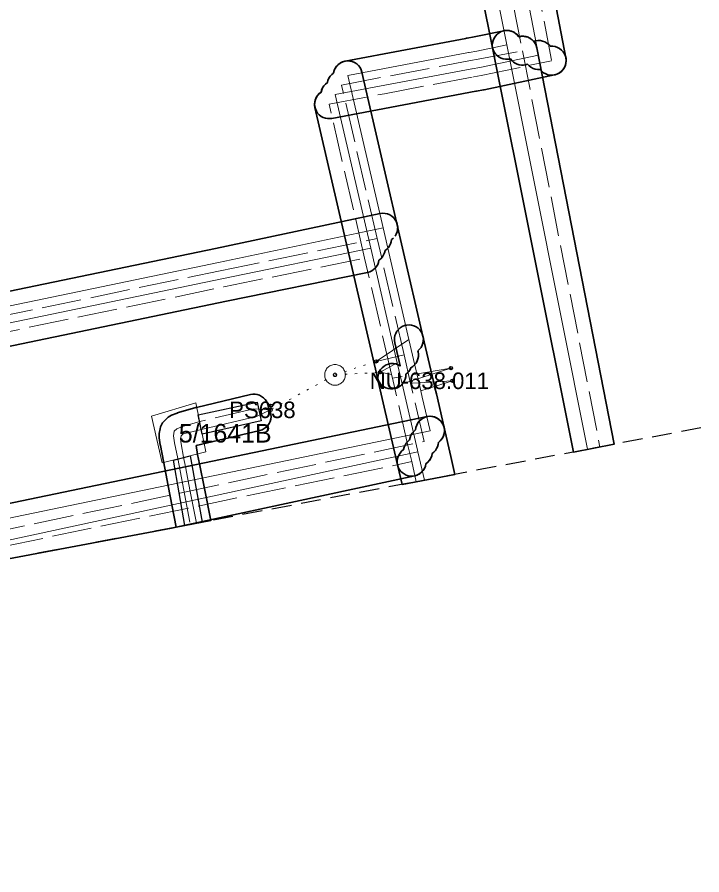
# Model space of a CAD drawing. Extents: x -452602 to -451136, y -1100088 to -1099653.
# Drawn here: x -451882.27 to -451849.14, y -1099973.17 to -1099931.68 of the extents above; entities that cross this region are included whole.
import ezdxf

# ---------------------------------------------------------------- set-up
doc = ezdxf.new("R2010")
doc.units = 0
doc.header["$LTSCALE"] = 0.32
doc.header["$PDMODE"] = 32
doc.header["$PDSIZE"] = 0.16
for name, pattern in [('DOTTED', [1.5, 0.3, -1.2]), ('LONG_DASHED', [7.5, 6, -1.5]), ('MEDIUM_DASHED', [4.5, 3, -1.5])]:
    doc.linetypes.add(name, pattern=pattern)
for name, color, linetype in [('1', 7, 'Continuous'), ('4', 7, 'Continuous'), ('7', 7, 'Continuous')]:
    doc.layers.add(name, color=color, linetype=linetype)
for name, color, linetype, lineweight in [('2', 7, 'Continuous', 13), ('3', 7, 'Continuous', 25), ('5', 7, 'Continuous', 13), ('62', 7, 'MEDIUM_DASHED', 25), ('8', 7, 'Continuous', 35)]:
    doc.layers.add(name, color=color, linetype=linetype, lineweight=lineweight)

msp = doc.modelspace()

# ---------------------------------------------------------------- linework, layer by layer
at = {"layer": '1'}
for p in [(-451864.903, -1099948.331), (-451864.706, -1099948.857)]:
    msp.add_point(p, dxfattribs=at)
at = {"layer": '2'}
for p, q in [((-451864.778, -1099902.248), (-451858.58, -1099933.019)), ((-451862.992, -1099903.201), (-451857.038, -1099933.512)), ((-451858.58, -1099933.019), (-451854.67, -1099952.584)), ((-451863.315, -1099947.27), (-451864.563, -1099941.87)), ((-451863.876, -1099948.397), (-451865.156, -1099942.858)), ((-451863.315, -1099947.27), (-451864.903, -1099948.331)), ((-451862.738, -1099949.763), (-451863.315, -1099947.27)), ((-451863.876, -1099948.397), (-451864.706, -1099948.857)), ((-451863.641, -1099949.411), (-451863.876, -1099948.397)), ((-451861.281, -1099948.654), (-451863.641, -1099949.411)), ((-451862.738, -1099949.763), (-451861.21, -1099949.269)), ((-451870.689, -1099950.989), (-451870.007, -1099950.674)), ((-451862.562, -1099954.077), (-451862.88, -1099952.702))]:
    msp.add_line(p, q, dxfattribs=at)
at = {"layer": '2', "linetype": 'LONG_DASHED'}
for p, q in [((-451863.866, -1099902.804), (-451857.821, -1099933.303)), ((-451862.199, -1099903.597), (-451856.41, -1099933.788)), ((-451857.821, -1099933.303), (-451854.074, -1099952.472)), ((-451863.551, -1099948.021), (-451864.854, -1099942.386)), ((-451864.156, -1099948.964), (-451865.455, -1099943.341)), ((-451863.551, -1099948.021), (-451864.903, -1099948.331)), ((-451863.233, -1099949.395), (-451863.551, -1099948.021)), ((-451864.156, -1099948.964), (-451864.706, -1099948.857)), ((-451864.115, -1099949.137), (-451864.156, -1099948.964)), ((-451861.281, -1099948.654), (-451864.115, -1099949.137)), ((-451861.21, -1099949.269), (-451863.233, -1099949.395)), ((-451862.583, -1099952.206), (-451863.233, -1099949.395)), ((-451870.82, -1099950.62), (-451870.007, -1099950.674)), ((-451862.956, -1099954.151), (-451863.18, -1099953.181))]:
    msp.add_line(p, q, dxfattribs=at)
at = {"layer": '2', "linetype": 'DOTTED'}
for q in [(-451864.903, -1099948.331), (-451870.007, -1099950.674), (-451864.706, -1099948.857)]:
    msp.add_line((-451866.89, -1099948.984), q, dxfattribs=at)
at = {"layer": '2'}
for points in [[(-451860.424, -1099933.39), (-451860.405, -1099933.386), (-451860.035, -1099933.326), (-451858.58, -1099933.019)], [(-451864.563, -1099941.87), (-451866.267, -1099934.499), (-451860.424, -1099933.39)], [(-451860.252, -1099934.173), (-451859.888, -1099934.114), (-451857.038, -1099933.512)], [(-451865.156, -1099942.858), (-451866.875, -1099935.429), (-451860.266, -1099934.175), (-451860.252, -1099934.173)], [(-451864.563, -1099941.87), (-451872.522, -1099943.554), (-451901.925, -1099949.652), (-451902.376, -1099947.344)], [(-451865.156, -1099942.858), (-451872.357, -1099944.337), (-451872.363, -1099944.337), (-451902.483, -1099950.597), (-451903.107, -1099947.495)], [(-451862.88, -1099952.702), (-451862.897, -1099952.63), (-451863.641, -1099949.411)], [(-451862.294, -1099951.684), (-451862.669, -1099950.062), (-451862.738, -1099949.763)], [(-451873.593, -1099956.163), (-451873.896, -1099954.62), (-451874.13, -1099953.427), (-451874.222, -1099952.958), (-451874.33, -1099952.315), (-451874.369, -1099952.078), (-451874.333, -1099951.934), (-451874.231, -1099951.841), (-451874.028, -1099951.784), (-451873.292, -1099951.606), (-451870.689, -1099950.989)], [(-451886.379, -1099958.581), (-451886.715, -1099956.758), (-451862.294, -1099951.684)], [(-451885.428, -1099958.401), (-451885.603, -1099957.604), (-451862.88, -1099952.702)]]:
    msp.add_lwpolyline(points, dxfattribs=at)
at = {"layer": '2', "linetype": 'LONG_DASHED'}
for points in [[(-451860.339, -1099933.78), (-451860.336, -1099933.78), (-451859.962, -1099933.719), (-451857.821, -1099933.303)], [(-451864.854, -1099942.386), (-451866.571, -1099934.964), (-451860.339, -1099933.78)], [(-451860.167, -1099934.563), (-451859.815, -1099934.506), (-451856.41, -1099933.788)], [(-451864.495, -1099935.384), (-451860.196, -1099934.568), (-451860.167, -1099934.563)], [(-451865.455, -1099943.341), (-451867.178, -1099935.892), (-451864.495, -1099935.384)], [(-451902.749, -1099947.447), (-451902.206, -1099950.14), (-451872.441, -1099943.945), (-451872.44, -1099943.945), (-451864.854, -1099942.386)], [(-451903.519, -1099947.567), (-451902.827, -1099951.079), (-451872.285, -1099944.73), (-451872.275, -1099944.728), (-451865.455, -1099943.341)], [(-451863.18, -1099953.181), (-451863.376, -1099952.332), (-451864.115, -1099949.137)], [(-451870.82, -1099950.62), (-451873.429, -1099951.239), (-451874.268, -1099951.479), (-451874.535, -1099951.585), (-451874.663, -1099951.713), (-451874.699, -1099951.934), (-451874.65, -1099952.264), (-451874.501, -1099953.029), (-451874.273, -1099954.214), (-451873.891, -1099956.219)], [(-451885.867, -1099958.484), (-451886.133, -1099957.181), (-451862.583, -1099952.206)], [(-451885.135, -1099958.345), (-451885.261, -1099957.769), (-451863.18, -1099953.181)]]:
    msp.add_lwpolyline(points, dxfattribs=at)
at = {"layer": '3', "lineweight": 13}
msp.add_lwpolyline([(-451875.25, -1099953.239), (-451875.774, -1099950.975), (-451873.63, -1099950.339), (-451873.14, -1099952.699)], close=True, dxfattribs=at)
at = {"layer": '3'}
for points in [[(-451873.51, -1099950.913), (-451870.663, -1099950.3), (-451870.462, -1099951.208), (-451873.317, -1099951.843)], [(-451874.154, -1099956.269), (-451874.711, -1099953.102), (-451873.897, -1099952.893), (-451873.317, -1099956.11)]]:
    msp.add_lwpolyline(points, close=True, dxfattribs=at)
at = {"layer": '4'}
for p in [(-451861.281, -1099948.654), (-451861.21, -1099949.269), (-451870.007, -1099950.674)]:
    msp.add_point(p, dxfattribs=at)
at = {"layer": '5'}
for points in [[(-451866.39, -1099948.984), (-451866.393, -1099948.932), (-451866.401, -1099948.88), (-451866.415, -1099948.829), (-451866.433, -1099948.781), (-451866.457, -1099948.734), (-451866.486, -1099948.69), (-451866.519, -1099948.65), (-451866.556, -1099948.613), (-451866.596, -1099948.579), (-451866.64, -1099948.551), (-451866.687, -1099948.527), (-451866.736, -1099948.508), (-451866.786, -1099948.494), (-451866.838, -1099948.487), (-451866.89, -1099948.484), (-451866.942, -1099948.487), (-451866.994, -1099948.494), (-451867.045, -1099948.508), (-451867.093, -1099948.527), (-451867.14, -1099948.551), (-451867.184, -1099948.579), (-451867.225, -1099948.613), (-451867.262, -1099948.65), (-451867.295, -1099948.69), (-451867.323, -1099948.734), (-451867.347, -1099948.781), (-451867.366, -1099948.829), (-451867.379, -1099948.88), (-451867.387, -1099948.932), (-451867.39, -1099948.984), (-451867.387, -1099949.035), (-451867.379, -1099949.088), (-451867.366, -1099949.139), (-451867.347, -1099949.187), (-451867.323, -1099949.234), (-451867.295, -1099949.278), (-451867.262, -1099949.319), (-451867.225, -1099949.356), (-451867.184, -1099949.389), (-451867.14, -1099949.417), (-451867.093, -1099949.44), (-451867.045, -1099949.46), (-451866.994, -1099949.473), (-451866.942, -1099949.481), (-451866.89, -1099949.484), (-451866.838, -1099949.481), (-451866.786, -1099949.473), (-451866.736, -1099949.46), (-451866.687, -1099949.44), (-451866.64, -1099949.417), (-451866.596, -1099949.389), (-451866.556, -1099949.356), (-451866.519, -1099949.319), (-451866.486, -1099949.278), (-451866.457, -1099949.234), (-451866.433, -1099949.187), (-451866.415, -1099949.139), (-451866.401, -1099949.088), (-451866.393, -1099949.035)], [(-451866.808, -1099948.984), (-451866.808, -1099948.974), (-451866.81, -1099948.967), (-451866.812, -1099948.959), (-451866.815, -1099948.951), (-451866.819, -1099948.943), (-451866.824, -1099948.936), (-451866.829, -1099948.929), (-451866.835, -1099948.923), (-451866.842, -1099948.917), (-451866.849, -1099948.913), (-451866.857, -1099948.909), (-451866.865, -1099948.906), (-451866.873, -1099948.903), (-451866.881, -1099948.902), (-451866.89, -1099948.902), (-451866.899, -1099948.902), (-451866.907, -1099948.903), (-451866.915, -1099948.906), (-451866.923, -1099948.909), (-451866.931, -1099948.913), (-451866.938, -1099948.917), (-451866.945, -1099948.923), (-451866.951, -1099948.929), (-451866.957, -1099948.936), (-451866.961, -1099948.943), (-451866.965, -1099948.951), (-451866.968, -1099948.959), (-451866.97, -1099948.967), (-451866.972, -1099948.974), (-451866.972, -1099948.984), (-451866.972, -1099948.993), (-451866.97, -1099949.001), (-451866.968, -1099949.008), (-451866.965, -1099949.017), (-451866.961, -1099949.025), (-451866.957, -1099949.032), (-451866.951, -1099949.038), (-451866.945, -1099949.045), (-451866.938, -1099949.051), (-451866.931, -1099949.055), (-451866.923, -1099949.059), (-451866.915, -1099949.062), (-451866.907, -1099949.064), (-451866.899, -1099949.065), (-451866.89, -1099949.065), (-451866.881, -1099949.065), (-451866.873, -1099949.064), (-451866.865, -1099949.062), (-451866.857, -1099949.059), (-451866.849, -1099949.055), (-451866.842, -1099949.051), (-451866.835, -1099949.045), (-451866.829, -1099949.038), (-451866.824, -1099949.032), (-451866.819, -1099949.025), (-451866.815, -1099949.017), (-451866.812, -1099949.008), (-451866.81, -1099949.001), (-451866.808, -1099948.993)]]:
    msp.add_lwpolyline(points, close=True, dxfattribs=at)
at = {"layer": '62'}
msp.add_lwpolyline([(-451137.485, -1099816.961), (-452572.169, -1100088.267), (-452602.314, -1099919.678), (-451137.485, -1099652.838), (-451136.368, -1099701.963)], close=True, dxfattribs=at)
at = {"layer": '7'}
msp.add_point((-451869.987, -1099950.476), dxfattribs=at)
at = {"layer": '8'}
for points in [[(-451861.511, -1099903.466), (-451855.722, -1099933.656), (-451855.71, -1099933.773), (-451855.717, -1099933.89), (-451855.744, -1099934.005), (-451855.789, -1099934.113), (-451855.853, -1099934.212), (-451855.931, -1099934.299), (-451856.024, -1099934.372), (-451856.127, -1099934.428), (-451856.238, -1099934.467), (-451856.354, -1099934.486), (-451856.471, -1099934.486), (-451856.586, -1099934.465), (-451856.697, -1099934.427), (-451856.799, -1099934.37), (-451856.891, -1099934.296), (-451856.969, -1099934.209), (-451856.983, -1099934.21), (-451857.094, -1099934.21), (-451857.205, -1099934.192), (-451857.311, -1099934.157), (-451857.41, -1099934.106), (-451857.5, -1099934.039), (-451857.577, -1099933.959), (-451857.67, -1099933.986), (-451857.765, -1099934.001), (-451857.87, -1099934.001), (-451857.974, -1099933.986), (-451858.075, -1099933.955), (-451858.17, -1099933.909), (-451858.257, -1099933.85), (-451858.334, -1099933.778), (-451858.4, -1099933.696), (-451858.462, -1099933.709), (-451858.524, -1099933.717), (-451858.637, -1099933.717), (-451858.748, -1099933.699), (-451858.855, -1099933.663), (-451858.955, -1099933.611), (-451859.045, -1099933.543), (-451859.123, -1099933.461), (-451859.187, -1099933.368), (-451859.235, -1099933.266), (-451859.266, -1099933.158), (-451865.465, -1099902.386)], [(-451858.025, -1099932.593), (-451858.002, -1099932.625), (-451857.954, -1099932.616), (-451857.912, -1099932.609), (-451857.866, -1099932.604), (-451857.821, -1099932.603), (-451857.775, -1099932.604), (-451857.729, -1099932.609), (-451857.684, -1099932.616), (-451857.64, -1099932.627), (-451857.596, -1099932.64), (-451857.553, -1099932.656), (-451857.511, -1099932.675), (-451857.471, -1099932.697), (-451857.432, -1099932.721), (-451857.395, -1099932.747), (-451857.359, -1099932.776), (-451857.326, -1099932.808), (-451857.294, -1099932.841), (-451857.288, -1099932.85), (-451857.183, -1099932.827), (-451857.07, -1099932.812), (-451856.956, -1099932.815), (-451856.844, -1099932.837), (-451856.737, -1099932.877), (-451856.638, -1099932.933), (-451856.549, -1099933.005), (-451856.473, -1099933.09), (-451856.355, -1099933.089), (-451856.239, -1099933.107), (-451856.127, -1099933.144), (-451856.023, -1099933.2), (-451855.929, -1099933.273), (-451855.85, -1099933.36), (-451855.786, -1099933.459), (-451855.739, -1099933.568), (-451855.712, -1099933.683), (-451855.704, -1099933.8), (-451855.717, -1099933.918), (-451855.748, -1099934.032), (-451855.799, -1099934.138), (-451855.867, -1099934.235), (-451855.95, -1099934.319), (-451856.046, -1099934.388), (-451856.152, -1099934.44), (-451856.265, -1099934.473), (-451859.671, -1099935.191), (-451859.686, -1099935.194), (-451859.704, -1099935.197), (-451860.049, -1099935.253), (-451860.056, -1099935.254), (-451860.072, -1099935.257), (-451867.047, -1099936.58), (-451867.122, -1099936.59), (-451867.237, -1099936.59), (-451867.35, -1099936.571), (-451867.459, -1099936.533), (-451867.56, -1099936.478), (-451867.651, -1099936.408), (-451867.729, -1099936.323), (-451867.792, -1099936.227), (-451867.839, -1099936.121), (-451867.868, -1099936.01), (-451867.877, -1099935.895), (-451867.868, -1099935.78), (-451867.84, -1099935.668), (-451867.795, -1099935.563), (-451867.732, -1099935.466), (-451867.655, -1099935.381), (-451867.564, -1099935.309), (-451867.536, -1099935.199), (-451867.49, -1099935.094), (-451867.427, -1099934.999), (-451867.35, -1099934.915), (-451867.26, -1099934.844), (-451867.232, -1099934.734), (-451867.186, -1099934.63), (-451867.124, -1099934.535), (-451867.047, -1099934.451), (-451866.957, -1099934.38), (-451866.927, -1099934.263), (-451866.876, -1099934.153), (-451866.807, -1099934.053), (-451866.722, -1099933.967), (-451866.624, -1099933.896), (-451866.515, -1099933.844), (-451866.398, -1099933.811), (-451860.568, -1099932.706), (-451860.554, -1099932.703), (-451860.541, -1099932.7), (-451860.489, -1099932.692), (-451860.164, -1099932.638), (-451858.725, -1099932.335), (-451858.717, -1099932.333), (-451858.671, -1099932.325), (-451858.626, -1099932.321), (-451858.58, -1099932.319), (-451858.534, -1099932.321), (-451858.489, -1099932.325), (-451858.443, -1099932.333)], [(-451858.399, -1099932.343), (-451858.355, -1099932.357), (-451858.312, -1099932.373), (-451858.27, -1099932.392), (-451858.23, -1099932.413), (-451858.191, -1099932.437), (-451858.154, -1099932.464), (-451858.119, -1099932.493), (-451858.085, -1099932.524), (-451858.054, -1099932.558), (-451858.025, -1099932.593)], [(-451901.374, -1099948.823), (-451872.665, -1099942.868), (-451864.708, -1099941.185), (-451864.589, -1099941.169), (-451864.469, -1099941.174), (-451864.351, -1099941.199), (-451864.24, -1099941.244), (-451864.137, -1099941.307), (-451864.048, -1099941.387), (-451863.973, -1099941.481), (-451863.915, -1099941.587), (-451863.876, -1099941.701), (-451863.858, -1099941.82), (-451863.86, -1099941.94), (-451863.882, -1099942.058), (-451863.925, -1099942.171), (-451863.986, -1099942.274)], [(-451864.064, -1099942.366), (-451864.156, -1099942.443), (-451864.173, -1099942.546), (-451864.204, -1099942.647), (-451864.251, -1099942.741), (-451864.31, -1099942.827), (-451864.382, -1099942.903), (-451864.465, -1099942.968), (-451864.492, -1099943.079), (-451864.537, -1099943.183), (-451864.597, -1099943.28), (-451864.673, -1099943.365), (-451864.762, -1099943.436), (-451864.784, -1099943.542), (-451864.823, -1099943.642), (-451864.877, -1099943.736), (-451864.945, -1099943.82), (-451865.024, -1099943.893), (-451865.114, -1099943.953), (-451865.212, -1099943.998), (-451865.316, -1099944.027), (-451872.136, -1099945.415), (-451872.145, -1099945.416)], [(-451872.145, -1099945.416), (-451902.685, -1099951.764)], [(-451886.857, -1099956.072), (-451862.436, -1099950.998), (-451862.318, -1099950.984), (-451862.2, -1099950.99), (-451862.083, -1099951.016), (-451861.973, -1099951.061), (-451861.873, -1099951.125), (-451861.784, -1099951.204), (-451861.71, -1099951.297), (-451861.653, -1099951.402), (-451861.615, -1099951.514), (-451861.596, -1099951.632), (-451861.597, -1099951.751), (-451861.619, -1099951.868), (-451861.659, -1099951.979), (-451861.719, -1099952.083), (-451861.795, -1099952.174), (-451861.885, -1099952.252), (-451861.899, -1099952.355), (-451861.929, -1099952.456), (-451861.974, -1099952.551), (-451862.032, -1099952.638), (-451862.103, -1099952.715), (-451862.184, -1099952.782), (-451862.208, -1099952.901), (-451862.253, -1099953.014), (-451862.316, -1099953.118), (-451862.397, -1099953.209), (-451862.492, -1099953.285), (-451862.52, -1099953.402), (-451862.568, -1099953.513), (-451862.633, -1099953.614), (-451862.715, -1099953.701), (-451862.811, -1099953.774), (-451862.918, -1099953.829), (-451863.033, -1099953.865), (-451874.807, -1099956.392), (-451887.066, -1099958.711)]]:
    msp.add_lwpolyline(points, dxfattribs=at)
for points in [[(-451858.003, -1099932.627), (-451857.89, -1099932.606), (-451857.776, -1099932.604), (-451857.662, -1099932.621), (-451857.553, -1099932.656), (-451857.451, -1099932.709), (-451857.358, -1099932.777), (-451857.279, -1099932.86), (-451857.214, -1099932.954), (-451857.165, -1099933.058), (-451857.134, -1099933.168), (-451853.386, -1099952.342), (-451855.358, -1099952.714), (-451859.266, -1099933.157), (-451859.279, -1099933.038), (-451859.271, -1099932.919), (-451859.243, -1099932.803), (-451859.196, -1099932.694), (-451859.131, -1099932.594), (-451859.05, -1099932.507), (-451858.955, -1099932.435), (-451858.85, -1099932.379), (-451858.736, -1099932.343), (-451858.618, -1099932.326), (-451858.499, -1099932.329), (-451858.382, -1099932.353), (-451858.271, -1099932.396), (-451858.169, -1099932.457), (-451858.079, -1099932.535)], [(-451864.1, -1099949.661), (-451864.21, -1099949.661), (-451864.319, -1099949.644), (-451864.425, -1099949.61), (-451864.523, -1099949.559), (-451864.612, -1099949.494), (-451864.69, -1099949.415), (-451864.755, -1099949.326), (-451864.804, -1099949.227), (-451864.837, -1099949.121), (-451867.859, -1099936.05), (-451867.876, -1099935.931), (-451867.872, -1099935.81), (-451867.847, -1099935.692), (-451867.802, -1099935.58), (-451867.738, -1099935.477), (-451867.658, -1099935.387), (-451867.564, -1099935.312), (-451867.535, -1099935.201), (-451867.489, -1099935.097), (-451867.427, -1099935.001), (-451867.349, -1099934.917), (-451867.26, -1099934.847), (-451867.231, -1099934.737), (-451867.186, -1099934.633), (-451867.124, -1099934.538), (-451867.048, -1099934.455), (-451866.959, -1099934.384), (-451866.93, -1099934.267), (-451866.881, -1099934.157), (-451866.814, -1099934.057), (-451866.73, -1099933.97), (-451866.633, -1099933.899), (-451866.525, -1099933.845), (-451866.41, -1099933.811), (-451866.29, -1099933.796), (-451866.17, -1099933.803), (-451866.053, -1099933.83), (-451865.941, -1099933.877), (-451865.84, -1099933.942), (-451865.751, -1099934.024), (-451865.678, -1099934.119), (-451865.622, -1099934.226), (-451865.586, -1099934.341), (-451862.633, -1099947.112), (-451862.616, -1099947.223), (-451862.618, -1099947.336), (-451862.637, -1099947.447), (-451862.675, -1099947.553), (-451862.728, -1099947.652), (-451862.797, -1099947.741), (-451862.88, -1099947.818), (-451862.869, -1099947.864), (-451862.853, -1099947.976), (-451862.854, -1099948.09), (-451862.875, -1099948.202), (-451862.913, -1099948.309), (-451862.968, -1099948.409), (-451863.039, -1099948.499), (-451863.123, -1099948.575), (-451863.218, -1099948.637), (-451863.26, -1099948.729), (-451863.314, -1099948.814), (-451863.38, -1099948.89), (-451863.456, -1099948.956), (-451863.464, -1099949.073), (-451863.492, -1099949.186), (-451863.538, -1099949.293), (-451863.601, -1099949.391), (-451863.68, -1099949.477), (-451863.772, -1099949.549), (-451863.874, -1099949.605), (-451863.984, -1099949.642)], [(-451862.633, -1099947.112), (-451862.062, -1099949.582), (-451862.056, -1099949.605), (-451861.987, -1099949.904), (-451861.612, -1099951.526), (-451861.608, -1099951.547), (-451861.6, -1099951.592), (-451861.596, -1099951.638), (-451861.594, -1099951.684), (-451861.596, -1099951.73), (-451861.6, -1099951.775), (-451861.608, -1099951.82), (-451861.618, -1099951.865), (-451861.631, -1099951.909), (-451861.647, -1099951.952), (-451861.666, -1099951.993), (-451861.688, -1099952.034), (-451861.712, -1099952.073), (-451861.739, -1099952.11), (-451861.768, -1099952.145), (-451861.799, -1099952.179), (-451861.833, -1099952.21), (-451861.868, -1099952.239), (-451861.885, -1099952.251), (-451861.899, -1099952.355), (-451861.929, -1099952.456), (-451861.974, -1099952.551), (-451862.032, -1099952.638), (-451862.103, -1099952.715), (-451862.184, -1099952.782), (-451862.208, -1099952.9), (-451862.252, -1099953.012), (-451862.315, -1099953.115), (-451862.394, -1099953.206), (-451862.488, -1099953.282), (-451862.514, -1099953.397), (-451862.56, -1099953.505), (-451862.623, -1099953.604), (-451862.702, -1099953.692), (-451862.794, -1099953.765), (-451862.897, -1099953.821), (-451863.008, -1099953.859), (-451863.124, -1099953.879), (-451863.235, -1099953.879), (-451863.344, -1099953.861), (-451863.449, -1099953.827), (-451863.548, -1099953.776), (-451863.637, -1099953.711), (-451863.715, -1099953.633), (-451863.779, -1099953.543), (-451863.829, -1099953.444), (-451863.862, -1099953.338), (-451864.059, -1099952.49), (-451864.797, -1099949.295), (-451864.815, -1099949.177), (-451864.812, -1099949.057), (-451864.789, -1099948.941), (-451864.746, -1099948.829), (-451864.685, -1099948.727), (-451864.608, -1099948.636), (-451864.516, -1099948.56), (-451864.413, -1099948.5), (-451864.301, -1099948.459), (-451864.184, -1099948.438), (-451864.065, -1099948.436), (-451863.947, -1099948.455), (-451863.834, -1099948.493), (-451863.738, -1099948.546), (-451863.997, -1099947.427), (-451864.014, -1099947.313), (-451864.012, -1099947.197), (-451863.991, -1099947.083), (-451863.951, -1099946.974), (-451863.894, -1099946.873), (-451863.821, -1099946.783), (-451863.734, -1099946.706), (-451863.636, -1099946.645), (-451863.529, -1099946.6), (-451863.416, -1099946.574), (-451863.3, -1099946.567), (-451863.185, -1099946.579), (-451863.073, -1099946.61), (-451862.968, -1099946.659), (-451862.873, -1099946.725), (-451862.789, -1099946.805), (-451862.72, -1099946.898), (-451862.668, -1099947.001)], [(-451874.579, -1099956.349), (-451874.961, -1099954.346), (-451875.188, -1099953.163), (-451875.337, -1099952.398), (-451875.342, -1099952.375), (-451875.343, -1099952.365), (-451875.391, -1099952.035), (-451875.399, -1099951.929), (-451875.39, -1099951.822), (-451875.354, -1099951.601), (-451875.328, -1099951.495), (-451875.286, -1099951.394), (-451875.229, -1099951.301), (-451875.158, -1099951.218), (-451875.03, -1099951.09), (-451874.958, -1099951.027), (-451874.878, -1099950.975), (-451874.792, -1099950.934), (-451874.526, -1099950.828), (-451874.506, -1099950.821), (-451874.461, -1099950.806), (-451873.622, -1099950.566), (-451873.593, -1099950.559), (-451870.981, -1099949.938), (-451870.871, -1099949.92), (-451870.759, -1099949.92), (-451870.648, -1099949.937), (-451870.542, -1099949.972), (-451870.442, -1099950.024), (-451870.352, -1099950.09), (-451870.274, -1099950.17), (-451870.209, -1099950.262), (-451870.16, -1099950.363), (-451870.128, -1099950.47), (-451870.113, -1099950.581), (-451870.054, -1099950.679), (-451870.012, -1099950.786), (-451869.988, -1099950.898), (-451869.983, -1099951.013), (-451869.996, -1099951.127), (-451870.028, -1099951.237), (-451870.078, -1099951.34), (-451870.144, -1099951.434), (-451870.224, -1099951.517), (-451870.316, -1099951.584), (-451870.419, -1099951.636), (-451870.528, -1099951.671), (-451873.129, -1099952.287), (-451873.606, -1099952.402), (-451873.534, -1099952.832), (-451873.443, -1099953.292), (-451873.209, -1099954.485), (-451872.905, -1099956.033)], [(-451863.644, -1099954.281), (-451863.862, -1099953.338), (-451863.88, -1099953.219), (-451863.876, -1099953.098), (-451863.852, -1099952.979), (-451863.808, -1099952.867), (-451863.745, -1099952.764), (-451863.665, -1099952.673), (-451863.571, -1099952.597), (-451863.544, -1099952.487), (-451863.501, -1099952.383), (-451863.44, -1099952.287), (-451863.366, -1099952.201), (-451863.278, -1099952.13), (-451863.255, -1099952.015), (-451863.214, -1099951.907), (-451863.155, -1099951.806), (-451863.081, -1099951.717), (-451862.992, -1099951.641), (-451862.975, -1099951.525), (-451862.939, -1099951.414), (-451862.884, -1099951.31), (-451862.813, -1099951.217), (-451862.728, -1099951.137), (-451862.63, -1099951.072), (-451862.523, -1099951.025), (-451862.41, -1099950.996), (-451862.293, -1099950.986), (-451862.177, -1099950.996), (-451862.063, -1099951.025), (-451861.956, -1099951.073), (-451861.859, -1099951.138), (-451861.773, -1099951.218), (-451861.703, -1099951.311), (-451861.648, -1099951.415), (-451861.612, -1099951.526), (-451861.286, -1099952.935), (-451861.087, -1099953.798)]]:
    msp.add_lwpolyline(points, close=True, dxfattribs=at)

# ---------------------------------------------------------------- texts
at = {"layer": '3'}
msp.add_text('5/1641B', height=0.9, dxfattribs=at).set_placement((-451874.443, -1099952.256))
at = {"layer": '4'}
for s, p in [('NU-638.011', (-451865.21, -1099949.669)), ('PS638 ', (-451872.007, -1099951.074))]:
    msp.add_text(s, height=0.8, dxfattribs=at).set_placement(p)

doc.saveas('drawing.dxf')
